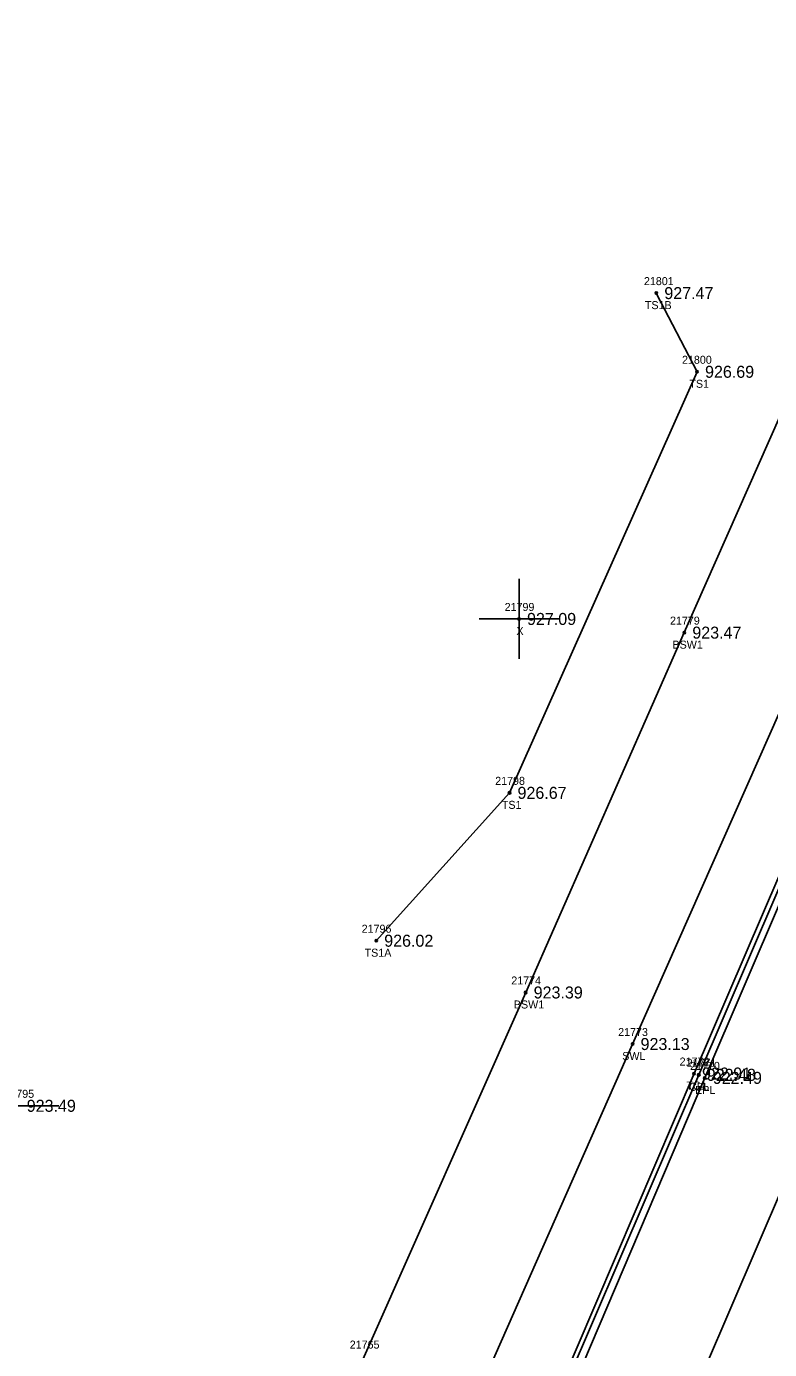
# Model space of a CAD drawing. Extents: x 1576181 to 1577685, y 1099396 to 1101490.
# Drawn here: x 1577074.4 to 1577167.3, y 1100920.8 to 1101086.2 of the extents above; entities that cross this region are included whole.
import ezdxf

# ---------------------------------------------------------------- set-up
doc = ezdxf.new("R2010")
doc.units = 0
for name, color, linetype in [('RD_DTM_BkLn1', 7, 'Continuous'), ('RD_DTM_BkLn2', 7, 'Continuous'), ('RD_DTM_BkLn_txCode', 7, 'Continuous'), ('RD_EX_Conc', 7, 'Continuous'), ('RD_EX_Conc_txCode', 7, 'Continuous'), ('RD_EX_Misc', 7, 'Continuous'), ('RD_EX_Misc_txCode', 7, 'Continuous'), ('RD_EX_Road', 7, 'Continuous'), ('RD_EX_Road_txCode', 7, 'Continuous'), ('RD_EX_TX_Conc_ELEV', 7, 'Continuous'), ('RD_EX_TX_Misc_ELEV', 7, 'Continuous'), ('RD_EX_TX_Road_ELEV', 7, 'Continuous'), ('RD_SMD_Locator', 7, 'Continuous')]:
    doc.layers.add(name, color=color, linetype=linetype)

msp = doc.modelspace()

# ---------------------------------------------------------------- linework, layer by layer
at = {"layer": 'RD_DTM_BkLn1'}
msp.add_lwpolyline([(1576908.25, 1100441.74), (1576920.44, 1100463.64), (1576944.47, 1100507.42), (1576973.89, 1100560.12), (1576993.13, 1100594.33), (1577014.77, 1100632.79), (1577042.14, 1100681.68), (1577066.82, 1100725.12), (1577089.75, 1100766.04), (1577111.87, 1100810.02), (1577132.74, 1100857.48), (1577152.58, 1100903.02), (1577172.32, 1100949.02), (1577191.93, 1100994.6), (1577211.77, 1101040.76), (1577222.24, 1101065.99), (1577231.17, 1101086.4), (1577251.41, 1101132.37), (1577271.56, 1101178.18), (1577291.61, 1101224.24), (1577311.77, 1101270.05), (1577333.79, 1101320.46), (1577355.93, 1101371.29), (1577365.01, 1101392.03)], dxfattribs=at)
at = {"layer": 'RD_DTM_BkLn2'}
for points in [[(1577118.14, 1100971.91), (1577134.8, 1100990.39), (1577158.24, 1101043.01), (1577153.15, 1101052.84)], [(1577107.29, 1100837.15), (1577118.47, 1100863.11), (1577138.23, 1100909.32), (1577157.86, 1100955.31), (1577177.11, 1101000.09), (1577190, 1101030.75)]]:
    msp.add_lwpolyline(points, dxfattribs=at)
at = {"layer": 'RD_EX_Conc'}
for points in [[(1577067.37, 1100812.25), (1577083.48, 1100844.88), (1577096.64, 1100874.51), (1577116.65, 1100919.94), (1577136.82, 1100965.44), (1577156.65, 1101010.41), (1577183.3, 1101070.64)], [(1577079.25, 1100805.08), (1577097.11, 1100838.84), (1577109.69, 1100867.34), (1577130.74, 1100915.04), (1577150.18, 1100959), (1577170.08, 1101003.92), (1577196.78, 1101064.66), (1577202.49, 1101060)], [(1577107.98, 1100836.94), (1577119.09, 1100862.85), (1577138.71, 1100909.15), (1577158.46, 1100955.15), (1577177.7, 1100999.96), (1577190.71, 1101030.46)]]:
    msp.add_lwpolyline(points, dxfattribs=at)
at = {"layer": 'RD_EX_Misc'}
for p, q in [((1577135.99, 1101007.12), (1577135.99, 1101017.12)), ((1577130.99, 1101012.12), (1577140.99, 1101012.12)), ((1577068.46, 1100951.28), (1577078.46, 1100951.28))]:
    msp.add_line(p, q, dxfattribs=at)
at = {"layer": 'RD_EX_Road'}
msp.add_lwpolyline([(1577060.61, 1100805.43), (1577075.53, 1100798.54), (1577081.93, 1100797.67), (1577087.92, 1100798.37), (1577091.21, 1100799.4), (1577094.49, 1100804.27), (1577106.9, 1100832.16), (1577119.9, 1100862.62), (1577139.86, 1100909.4), (1577159.21, 1100954.77), (1577178.5, 1100999.73), (1577192.43, 1101032.31), (1577206.43, 1101064.72)], dxfattribs=at)
at = {"layer": 'RD_SMD_Locator'}
for centre in [(1577153.15, 1101052.84), (1577158.24, 1101043.01), (1577135.99, 1101012.12), (1577156.65, 1101010.41), (1577134.8, 1100990.39), (1577118.14, 1100971.91), (1577136.82, 1100965.44), (1577150.18, 1100959), (1577157.86, 1100955.31), (1577158.46, 1100955.15), (1577159.21, 1100954.77)]:
    msp.add_circle(centre, 0.15, dxfattribs=at)

# ---------------------------------------------------------------- texts
at = {"layer": 'RD_DTM_BkLn_txCode'}
for s, p in [('21801', (1577151.6, 1101053.84)), ('TS1B', (1577151.72, 1101050.84)), ('21800', (1577156.36, 1101044.01)), ('TS1', (1577157.28, 1101041.01)), ('21798', (1577133.01, 1100991.39)), ('TS1', (1577133.84, 1100988.39)), ('21796', (1577116.32, 1100972.91)), ('TS1A', (1577116.69, 1100969.91))]:
    msp.add_text(s, height=1, dxfattribs=at).set_placement(p)
at = {"layer": 'RD_EX_Conc_txCode'}
for s, p in [('21779', (1577154.86, 1101011.41)), ('BSW1', (1577155.17, 1101008.41)), ('21774', (1577135.02, 1100966.44)), ('BSW1', (1577135.34, 1100963.44)), ('21773', (1577148.38, 1100960)), ('SWL', (1577148.89, 1100957)), ('21772', (1577156.06, 1100956.31)), ('21771', (1577156.94, 1100956.15)), ('TC1', (1577156.9, 1100953.31)), ('CFL', (1577157.25, 1100953.15)), ('21765', (1577114.83, 1100920.94))]:
    msp.add_text(s, height=1, dxfattribs=at).set_placement(p)
at = {"layer": 'RD_EX_Misc_txCode'}
for s, p in [('21799', (1577134.19, 1101013.12)), ('X', (1577135.67, 1101010.12)), ('21795', (1577071.66, 1100952.28))]:
    msp.add_text(s, height=1, dxfattribs=at).set_placement(p)
at = {"layer": 'RD_EX_Road_txCode'}
for s, p in [('21770', (1577157.37, 1100955.77)), ('EPL', (1577158, 1100952.77))]:
    msp.add_text(s, height=1, dxfattribs=at).set_placement(p)
at = {"layer": 'RD_EX_TX_Conc_ELEV'}
for s, p in [('923.47', (1577157.65, 1101009.66)), ('923.39', (1577137.82, 1100964.69)), ('923.13', (1577151.18, 1100958.25)), ('922.91', (1577158.86, 1100954.56)), ('922.48', (1577159.46, 1100954.4))]:
    msp.add_text(s, height=1.5, dxfattribs=at).set_placement(p)
at = {"layer": 'RD_EX_TX_Misc_ELEV'}
for s, p in [('927.47', (1577154.15, 1101052.09)), ('926.69', (1577159.24, 1101042.26)), ('927.09', (1577136.99, 1101011.37)), ('926.67', (1577135.8, 1100989.64)), ('926.02', (1577119.14, 1100971.16)), ('923.49', (1577074.46, 1100950.53))]:
    msp.add_text(s, height=1.5, dxfattribs=at).set_placement(p)
at = {"layer": 'RD_EX_TX_Road_ELEV'}
msp.add_text('922.49', height=1.5, dxfattribs=at).set_placement((1577160.21, 1100954.02))

doc.saveas('drawing.dxf')
